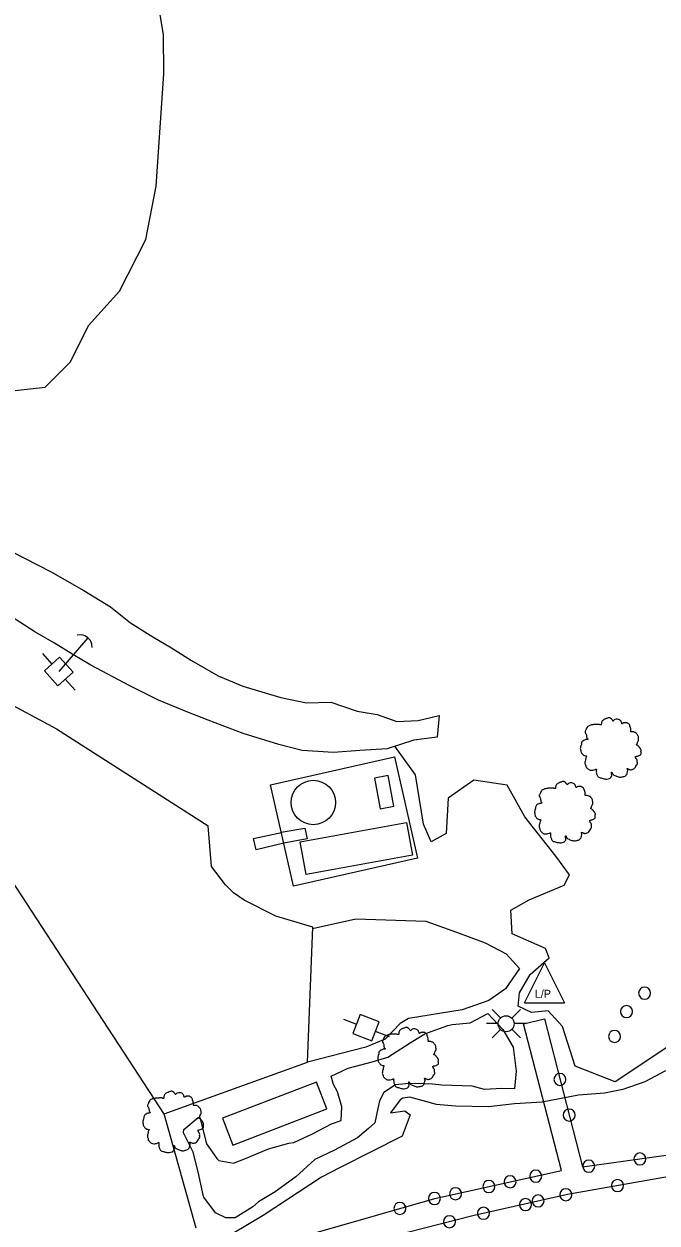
# Model space of a CAD drawing. Extents: x 2160437 to 2172832, y 205694 to 212444.
# Drawn here: x 2161366.8 to 2161525, y 210690.7 to 210990.4 of the extents above; entities that cross this region are included whole.
import ezdxf

# ---------------------------------------------------------------- set-up
doc = ezdxf.new("R2010")
doc.units = 0
for name, color, linetype in [('Default', 7, 'Continuous'), ('RD_EX_Bldg', 7, 'Continuous'), ('RD_EX_Bldg_Walls', 7, 'Continuous'), ('RD_EX_BldgApp', 7, 'Continuous'), ('RD_EX_Dam', 7, 'Continuous'), ('RD_EX_Driveway', 7, 'Continuous'), ('RD_EX_H2O', 7, 'Continuous'), ('RD_EX_LaneStripe', 7, 'Continuous'), ('RD_EX_Road_Post', 7, 'Continuous'), ('RD_EX_UT', 7, 'Continuous'), ('RD_EX_UT_Guy', 7, 'Continuous'), ('RD_EX_UT_GuyWire', 7, 'Continuous'), ('RD_EX_VEG', 7, 'Continuous'), ('RD_EX_VEG_ShrubLine', 7, 'Continuous'), ('RD_EX_VEG_TreeLine', 7, 'Continuous')]:
    doc.layers.add(name, color=color, linetype=linetype)

# ---------------------------------------------------------------- blocks, each defined once
blk = doc.blocks.new('GW')
at = {"layer": 'Default'}
for points in [[(0.0202, 0.0405), (0.0091, 0.0303)], [(0.008, -0.0285), (0.0202, -0.0407)]]:
    blk.add_lwpolyline(points, dxfattribs=at)
blk.add_arc((0.0545, 0), 0.0546, 146.3131, 211.4651, dxfattribs=at)
blk = doc.blocks.new('POST')
at = {"layer": 'Default'}
for start, end in [(90, 270), (270, 90)]:
    blk.add_arc((0, 0), 0.0417, start, end, dxfattribs=at)
blk = doc.blocks.new('T2')
at = {"layer": 'RD_EX_VEG'}
for points in [[(0.05, 7.21), (-0.25, 7.24), (-0.57, 7.14), (-0.82, 7.04), (-1.05, 6.96), (-1.27, 6.86), (-1.57, 6.69), (-1.8, 6.49), (-1.92, 6.24), (-1.97, 6.01), (-2.02, 5.74), (-2.02, 5.56), (-2.15, 5.54), (-2.3, 5.56), (-2.55, 5.64), (-2.8, 5.64), (-3.05, 5.64), (-3.4, 5.61), (-3.75, 5.61), (-4.02, 5.56), (-4.35, 5.51), (-4.72, 5.39), (-5.07, 5.26), (-5.37, 5.01), (-5.62, 4.54), (-5.75, 4.19), (-5.9, 3.94), (-5.75, 3.49), (-5.57, 3.14), (-5.55, 2.94), (-5.47, 2.52), (-5.37, 2.29), (-5.25, 2.09), (-5.32, 2.07), (-5.7, 2.02), (-6, 1.92), (-6.42, 1.69), (-6.64, 1.47), (-6.74, 1.14), (-6.77, 0.79), (-6.87, 0.59), (-6.94, 0.32), (-6.97, 0.24), (-7.02, -0.08), (-6.92, -0.53), (-6.89, -0.88), (-6.77, -1.11), (-6.62, -1.28), (-6.44, -1.53), (-6.05, -1.76), (-5.72, -1.86), (-5.52, -1.88), (-5.7, -2.38), (-5.75, -2.73), (-5.87, -3.13), (-5.87, -3.21), (-5.92, -3.68), (-5.77, -4.01), (-5.7, -4.38), (-5.52, -4.61), (-5.25, -4.91), (-4.92, -5.13), (-4.42, -5.26), (-4.02, -5.23), (-3.45, -5.06), (-3.2, -4.98), (-3.22, -5.16), (-3.2, -5.53), (-3.2, -5.96), (-3.05, -6.28), (-2.95, -6.56), (-2.8, -6.81), (-2.47, -7.03), (-2.07, -7.11), (-1.65, -7.26), (-1.2, -7.33), (-0.7, -7.36), (-0.1, -7.21), (0.18, -7.08), (0.28, -6.91), (0.48, -6.53), (0.43, -6.31), (0.45, -5.71), (0.55, -5.88), (0.73, -6.23), (1.23, -6.53), (1.63, -6.71), (2.1, -6.86), (2.4, -6.93), (2.88, -6.86), (3.25, -6.78), (3.63, -6.66), (3.93, -6.38), (4.1, -6.11), (4.15, -5.83), (4.23, -5.46), (4.28, -5.28)], [(4.28, -5.28), (4.2, -5.11), (4.15, -4.86), (4.23, -4.88), (4.4, -4.93), (4.68, -5.06), (4.9, -5.13), (5.23, -5.11), (5.5, -5.01), (5.95, -4.73), (6.22, -4.26), (6.5, -3.86), (6.57, -3.53), (6.52, -3.31), (6.5, -2.81), (6.3, -2.56), (6.25, -2.43), (6.15, -2.03), (6.22, -1.98), (6.5, -1.93), (6.87, -1.81), (7.15, -1.68), (7.37, -1.51), (7.45, -1.28), (7.42, -0.88), (7.47, -0.48), (7.4, -0.33), (7.3, -0.18), (7.22, 0.02), (7.07, 0.17), (6.97, 0.32), (6.87, 0.42), (6.75, 0.57), (6.57, 0.69), (6.42, 0.74), (6.37, 0.89), (6.52, 1.09), (6.57, 1.19), (6.6, 1.42), (6.82, 1.77), (6.87, 2.17), (6.82, 2.59), (6.77, 2.87), (6.62, 3.14), (6.42, 3.39), (6.3, 3.56), (6.12, 3.69), (5.8, 3.81), (5.55, 3.86), (5.2, 3.86), (5, 3.91), (5.03, 3.96), (5.03, 4.11), (5.03, 4.39), (4.95, 4.84), (4.8, 5.34), (4.8, 5.36), (4.7, 5.61), (4.48, 5.81), (4.3, 5.91), (4.1, 6.04), (3.85, 6.06), (3.55, 6.06), (3.28, 6.01), (3.08, 5.91), (2.9, 5.79), (2.83, 5.94), (2.73, 6.24), (2.68, 6.39), (2.53, 6.56), (2.3, 6.76), (1.85, 6.89), (1.23, 6.81), (0.93, 6.61), (0.78, 6.44), (0.73, 6.56), (0.53, 6.76), (0.43, 6.94), (0.25, 7.06), (0.1, 7.16), (0, 7.21)]]:
    blk.add_spline(points, degree=3, dxfattribs=at)
blk = doc.blocks.new('PP')
at = {"layer": 'RD_EX_UT'}
for p, q in [((2.49, 2.51), (-2.51, 2.51)), ((-2.51, 2.51), (-2.51, -2.49)), ((2.49, -2.49), (2.49, 2.51)), ((-5.94, -0.05), (-2.47, -0.05)), ((-2.51, -2.49), (2.49, -2.49)), ((2.42, -0.05), (6.06, -0.05))]:
    blk.add_line(p, q, dxfattribs=at)

msp = doc.modelspace()

# ---------------------------------------------------------------- linework, layer by layer
at = {"layer": 'RD_EX_Bldg'}
for points in [[(2161454.42, 210801.92), (2161455.86, 210794.25), (2161459.28, 210794.89), (2161457.84, 210802.56)], [(2161435.84, 210785.97), (2161462.45, 210790.77), (2161463.92, 210782.62), (2161437.31, 210777.81)], [(2161439.89, 210725.92), (2161416.38, 210716.87), (2161418.96, 210710.18), (2161442.46, 210719.23)]]:
    msp.add_lwpolyline(points, close=True, dxfattribs=at)
msp.add_circle((2161439.12, 210795.81), 5.55, dxfattribs=at)
at = {"layer": 'RD_EX_Bldg_Walls'}
msp.add_lwpolyline([(2161428.45, 210800.23), (2161459.42, 210807.23), (2161465.15, 210781.87), (2161434.19, 210774.87)], close=True, dxfattribs=at)
at = {"layer": 'RD_EX_BldgApp'}
msp.add_lwpolyline([(2161431.12, 210788.43), (2161437.02, 210789.38), (2161437.6, 210786.7), (2161431.76, 210785.62), (2161424.84, 210783.94), (2161424.19, 210786.81), (2161431.16, 210788.28)], dxfattribs=at)
at = {"layer": 'RD_EX_Dam'}
msp.add_lwpolyline([(2161411.23, 210678.11), (2161439.84, 210688.32), (2161469.52, 210696.85), (2161501.13, 210703.81), (2161491.66, 210740.45), (2161496.88, 210741.73), (2161506.42, 210704.69), (2161553.04, 210711.22), (2161569.64, 210714.16), (2161603.21, 210714.77), (2161637.76, 210716.14), (2161655.22, 210718.49), (2161692.81, 210718.11), (2161692.39, 210710.07), (2161667.04, 210712.66), (2161647.41, 210711.91), (2161623.03, 210710.09), (2161583.43, 210708.12), (2161562.36, 210707.65), (2161535.27, 210703.6), (2161502.64, 210697.85), (2161479.35, 210692.6), (2161449.92, 210685.03), (2161411.97, 210672.3)], dxfattribs=at)
at = {"layer": 'RD_EX_Driveway'}
for points in [[(2161218.31, 210999.33), (2161236.44, 210964.63), (2161253.03, 210934.01), (2161270.92, 210906.01), (2161287.83, 210884.31), (2161301.65, 210868.71), (2161313.66, 210857.75), (2161337.45, 210840.85), (2161360.55, 210821.88), (2161374.92, 210814.19), (2161412.79, 210789.94)], [(2161409.81, 210689.4), (2161401.82, 210717.98), (2161437.65, 210730.9), (2161438.96, 210764.61), (2161429.75, 210767.39), (2161421.84, 210771.37), (2161419.17, 210773.26), (2161417.2, 210775.22), (2161413.65, 210779.81), (2161412.79, 210789.94)], [(2161438.95, 210764.34), (2161449.72, 210766.76), (2161467.22, 210766.15), (2161474.92, 210763.43), (2161482.1, 210760.69), (2161487.33, 210757.95), (2161490.66, 210754.31), (2161487.17, 210749.23), (2161483, 210746.27), (2161476.33, 210744), (2161462.9, 210741.83), (2161460.8, 210740.52), (2161457.04, 210736.63), (2161452.24, 210734.65)], [(2161452.24, 210734.65), (2161437.65, 210730.9)]]:
    msp.add_lwpolyline(points, dxfattribs=at)
at = {"layer": 'RD_EX_H2O'}
msp.add_lwpolyline([(2161527.19, 210728.73), (2161521.99, 210725.99), (2161516.53, 210724.05), (2161511.93, 210723.18), (2161505.41, 210722.66), (2161496.33, 210720.92), (2161489.41, 210720.47), (2161482.9, 210719.7), (2161474.64, 210719.91), (2161469.91, 210720.29), (2161463.28, 210722.15), (2161461.52, 210721.88), (2161460.79, 210721.51), (2161458.41, 210718.19), (2161461.98, 210718.72), (2161463.35, 210717.72), (2161461.33, 210712.41), (2161445.85, 210704.57), (2161441.13, 210702.18), (2161426.6, 210692.54), (2161419.16, 210688.17)], dxfattribs=at)
at = {"layer": 'RD_EX_LaneStripe'}
msp.add_lwpolyline([(2161208.33, 210990.41), (2161244.14, 210927.49), (2161277.9, 210871.59), (2161300.83, 210845.97), (2161344.34, 210805.84), (2161401.86, 210717.85)], dxfattribs=at)
at = {"layer": 'RD_EX_UT'}
for p, q in [((2161491.92, 210745.71), (2161496.92, 210755.71)), ((2161496.92, 210755.71), (2161501.92, 210745.71)), ((2161491.92, 210745.71), (2161501.92, 210745.71)), ((2161483.84, 210744.06), (2161485.94, 210741.97)), ((2161488.75, 210741.9), (2161490.92, 210744.06)), ((2161485.31, 210740.53), (2161482.38, 210740.53)), ((2161483.84, 210736.99), (2161485.92, 210739.07)), ((2161488.77, 210739.14), (2161490.92, 210736.99)), ((2161492.38, 210740.53), (2161489.31, 210740.53))]:
    msp.add_line(p, q, dxfattribs=at)
msp.add_circle((2161487.31, 210740.51), 2, dxfattribs=at)
at = {"layer": 'RD_EX_UT_Guy'}
msp.add_lwpolyline([(2161382.72, 210837.01), (2161375.49, 210828.54)], dxfattribs=at)
at = {"layer": 'RD_EX_VEG_ShrubLine'}
for points in [[(2161249.84, 210996.14), (2161249.78, 210987.94), (2161254.98, 210972.02), (2161260.47, 210951.76), (2161268.33, 210933.13), (2161280.52, 210917.82), (2161293.37, 210904.54), (2161296.76, 210904.96), (2161298.96, 210912.89), (2161296.41, 210921.71), (2161307.68, 210915.93), (2161323.46, 210908.43), (2161344.54, 210901.67), (2161357.39, 210899.95), (2161364.61, 210898.83), (2161372.09, 210899.66), (2161378.45, 210905.96), (2161382.94, 210915.06), (2161390.65, 210923.64), (2161397.23, 210936.56), (2161399.86, 210949.89), (2161401.75, 210978), (2161401.64, 210987.79), (2161398.87, 211004.62)], [(2161529.21, 210735.71), (2161514.57, 210725.99), (2161504.58, 210729.87), (2161501.44, 210739.77), (2161497.83, 210743.73), (2161493.69, 210743.33), (2161490.32, 210744.92), (2161490.7, 210748.26), (2161493.32, 210752.8), (2161498.1, 210756.99), (2161497.14, 210759.3), (2161488.81, 210763), (2161488.48, 210768.93), (2161493.07, 210771.45), (2161501.79, 210775.17), (2161503.15, 210777.76), (2161499.76, 210782.37), (2161492.02, 210792.22), (2161487.55, 210800.14), (2161479.27, 210801.43), (2161472.84, 210796.92), (2161472.32, 210788.1), (2161468.61, 210786.01), (2161466.64, 210790.42), (2161464.66, 210802.74), (2161459.52, 210809.85)]]:
    msp.add_lwpolyline(points, dxfattribs=at)
msp.add_lwpolyline([(2161482.78, 210743.1), (2161486.48, 210739.05), (2161489.09, 210734.67), (2161489.09, 210734.67), (2161489.84, 210728.67), (2161489.42, 210724.27), (2161486.24, 210724.33), (2161481.9, 210724.03), (2161478.79, 210724.93), (2161471.22, 210725.14), (2161468.95, 210725.41), (2161464.69, 210725.58), (2161462.26, 210725.48), (2161459.68, 210725.2), (2161456.76, 210723.31), (2161455.69, 210721.22), (2161455.28, 210719.33), (2161454.52, 210715.72), (2161452.89, 210714.32), (2161450.13, 210711.98), (2161444.41, 210708.91), (2161439.53, 210706.59), (2161434.73, 210702.22), (2161429.58, 210698.46), (2161425.44, 210695.99), (2161423.96, 210694.77), (2161419.55, 210691.99), (2161417.25, 210692.02), (2161414.66, 210693.25), (2161411.76, 210697.14), (2161411.66, 210697.31), (2161410.34, 210703.44), (2161409.06, 210708.41), (2161406.64, 210713.21), (2161406.77, 210714.03), (2161410.34, 210717.07), (2161410.72, 210717.09), (2161412.39, 210710.49), (2161415.02, 210706.85), (2161415.53, 210706.31), (2161419.17, 210705.61), (2161422.17, 210706.83), (2161427.92, 210709.26), (2161432.99, 210710.61), (2161434.27, 210710.79), (2161438.92, 210713.02), (2161443.67, 210715.47), (2161446.07, 210716.33), (2161446.24, 210719.77), (2161445.14, 210723.47), (2161444.2, 210725.28), (2161443.58, 210727.38), (2161447.81, 210729.37), (2161453.87, 210730.97), (2161457.74, 210732.17), (2161458.94, 210732.88), (2161463.29, 210735.7), (2161467.27, 210738.11), (2161467.65, 210738.25), (2161472.73, 210740.04), (2161473.8, 210740.31), (2161478.37, 210740.7)], close=True, dxfattribs=at)
at = {"layer": 'RD_EX_VEG_TreeLine'}
msp.add_lwpolyline([(2161363.87, 210858.48), (2161373.44, 210853.52), (2161381.73, 210848.78), (2161388.45, 210844.74), (2161393.43, 210840.73), (2161399, 210837.21), (2161403.67, 210834.47), (2161408.67, 210831.34), (2161415.33, 210827.45), (2161421.48, 210824.92), (2161430.97, 210822.02), (2161437.43, 210820.74), (2161443.53, 210820.88), (2161450.07, 210818.67), (2161455.08, 210817.79), (2161459.97, 210816.09), (2161465.34, 210816.3), (2161470.57, 210817.59), (2161470.12, 210812.14), (2161464.25, 210811.39), (2161457.62, 210809.23), (2161450.77, 210808.81), (2161444.13, 210808.29), (2161436.32, 210808.8), (2161430.46, 210810.31), (2161430.46, 210810.31), (2161421.54, 210813.08), (2161412.85, 210816.38), (2161407.95, 210818.34), (2161400.4, 210821.37), (2161393.23, 210824.99), (2161383.49, 210830.14), (2161379.03, 210832.78), (2161374.41, 210835.62), (2161369.53, 210838.45), (2161360.75, 210844.05)], dxfattribs=at)

# ---------------------------------------------------------------- block references
at = {"layer": 'RD_EX_Road_Post', "xscale": 36, "yscale": 36}
for p in [(2161521.95, 210748.14), (2161517.42, 210743.53), (2161514.43, 210737.33), (2161500.78, 210726.59), (2161503.08, 210717.67), (2161507.96, 210704.9), (2161520.78, 210706.7), (2161488.31, 210700.99), (2161494.71, 210702.4), (2161474.68, 210697.99), (2161483.01, 210699.82), (2161502.24, 210697.76), (2161515.16, 210700.05), (2161469.4, 210696.81), (2161492.16, 210695.29), (2161495.31, 210696.2), (2161460.76, 210694.33), (2161481.66, 210693.12), (2161473.17, 210691.01)]:
    msp.add_blockref('POST', p, dxfattribs=at)
at = {"layer": 'RD_EX_UT', "xscale": 1.02}
for p, yscale, rotation in [((2161375.49, 210828.54), 1.0199999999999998, -48.25910499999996), ((2161452.31, 210739.54), 1.02, -21.010906)]:
    msp.add_blockref('PP', p, dxfattribs=dict(at, yscale=yscale, rotation=rotation))
at = {"layer": 'RD_EX_UT_GuyWire', "xscale": 60, "yscale": 60, "rotation": -129.88727000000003}
msp.add_blockref('GW', (2161382.72, 210837.01), dxfattribs=at)
at = {"layer": 'RD_EX_VEG', "xscale": 1.0499999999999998, "yscale": 1.0499999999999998}
for p in [(2161513.24, 210809.4), (2161501.78, 210793.47), (2161462.58, 210731.99), (2161403.85, 210716.03)]:
    msp.add_blockref('T2', p, dxfattribs=at)

# ---------------------------------------------------------------- texts
at = {"layer": 'RD_EX_UT'}
msp.add_text('L/P', height=2, dxfattribs=at).set_placement((2161494.52, 210746.99))

doc.saveas('drawing.dxf')
